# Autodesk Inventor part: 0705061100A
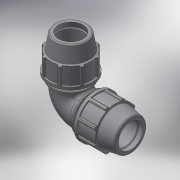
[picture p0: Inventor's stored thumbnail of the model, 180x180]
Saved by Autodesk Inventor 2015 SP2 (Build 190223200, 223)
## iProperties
Created: 2017-02
Part Number: 0705061100A
Material: Generic
Description: PLASSON 90° ELBOW 110-110
Document SubType Name: Modeling
Designer: KIM
Mass: 1923.39 g
Surface Area: 2516.77 cm^2
Volume: 1923.39 cm^3
Density: 1 g/cm^3
Appearance: Default
Author: KIM
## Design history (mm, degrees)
derived "87050.ipt"
feature "Solid1::87050.ipt"
tag "TaggingFeature1"
body "Solid1"
other parameters: "d4" = 24.33333, "d5" = 73, "d7" = 181, "d9" = 41.71429, "d11" = 11.68, "d13" = 120 deg, "d14" = 143, "d15" = 10 deg, "d16" = 166.52, "d18" = 5.5, "d19" = 35 deg, "d20" = 17.5 deg, "d21" = 168.33, "d23" = 0, "d25" = 360 deg, "d27" = 3.62, "d33" = 2.2, "d42" = 99.28, "d43" = 5.43, "d46" = 3.3, "d51" = 292, "d59" = 90 deg, "d63" = 194, "d64" = 99, "d67" = 135.75, "d68" = 21.024, "d70" = 90 deg, "d71" = 16.5, "d72" = 12.06667, "d73" = 0, "d75" = 90 deg, "d77" = 163.1896, "d78" = 7.008, "E_" = 181, "A_" = 292, "l_" = 194
